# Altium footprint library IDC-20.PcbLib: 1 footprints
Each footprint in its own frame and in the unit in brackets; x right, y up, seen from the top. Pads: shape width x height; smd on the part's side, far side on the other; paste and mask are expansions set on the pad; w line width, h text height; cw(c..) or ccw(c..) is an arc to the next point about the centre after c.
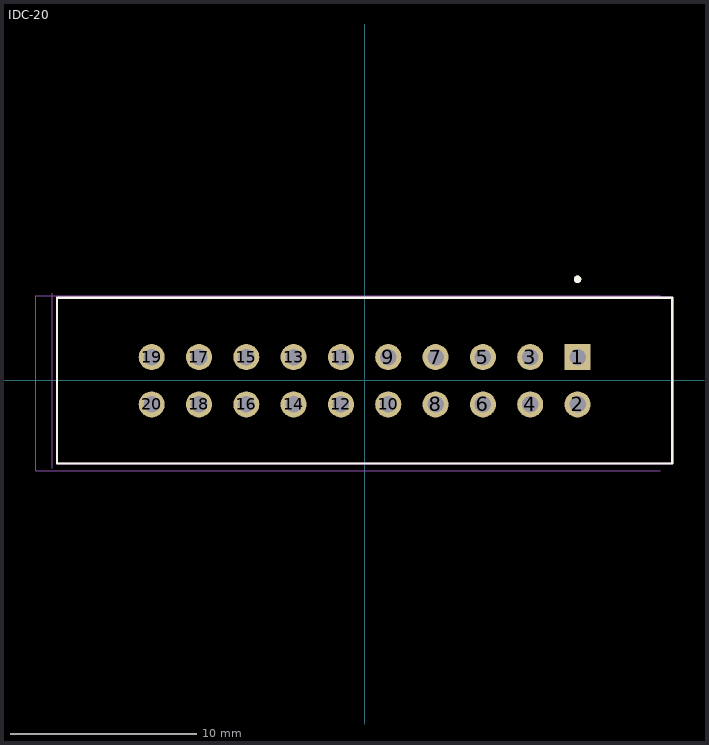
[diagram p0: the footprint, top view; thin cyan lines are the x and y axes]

## IDC-20 [mil]
pads (20):
  rect 55.04x55.04 hole 35.04: 1(450,49)
  round 55.04 hole 35.04: 2(450,-51) 3(350,49) 4(350,-51) 5(250,49) 6(250,-51) 7(150,49) 8(150,-51) 9(50,49) 10(50,-51) 11(-50,49) 12(-50,-51) 13(-150,49) 14(-150,-51) 15(-250,49) 16(-250,-51) 17(-350,49) 18(-350,-51) 19(-450,49) 20(-450,-51)
Top Overlay:
  circle w7.87: c450,213.37 r3.94
  lines w5: -650,-176 -650,174 650,174 650,-176 -650,-176
Mechanical 13:
  circle w7.87: c450,213.37 r3.94
  lines w5: -650,-176 -650,174 650,174 650,-176 -650,-176
Mechanical 15:
  lines w1.97: -659.84,-185.84 -659.84,183.84 ; 624.84,-190.84 -694.84,-190.84 -694.84,178.84 624.84,178.84
3D body "IDC-20.STEP": height 370, standoff -158, extent -647.87,-184.86 652.13,178.14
